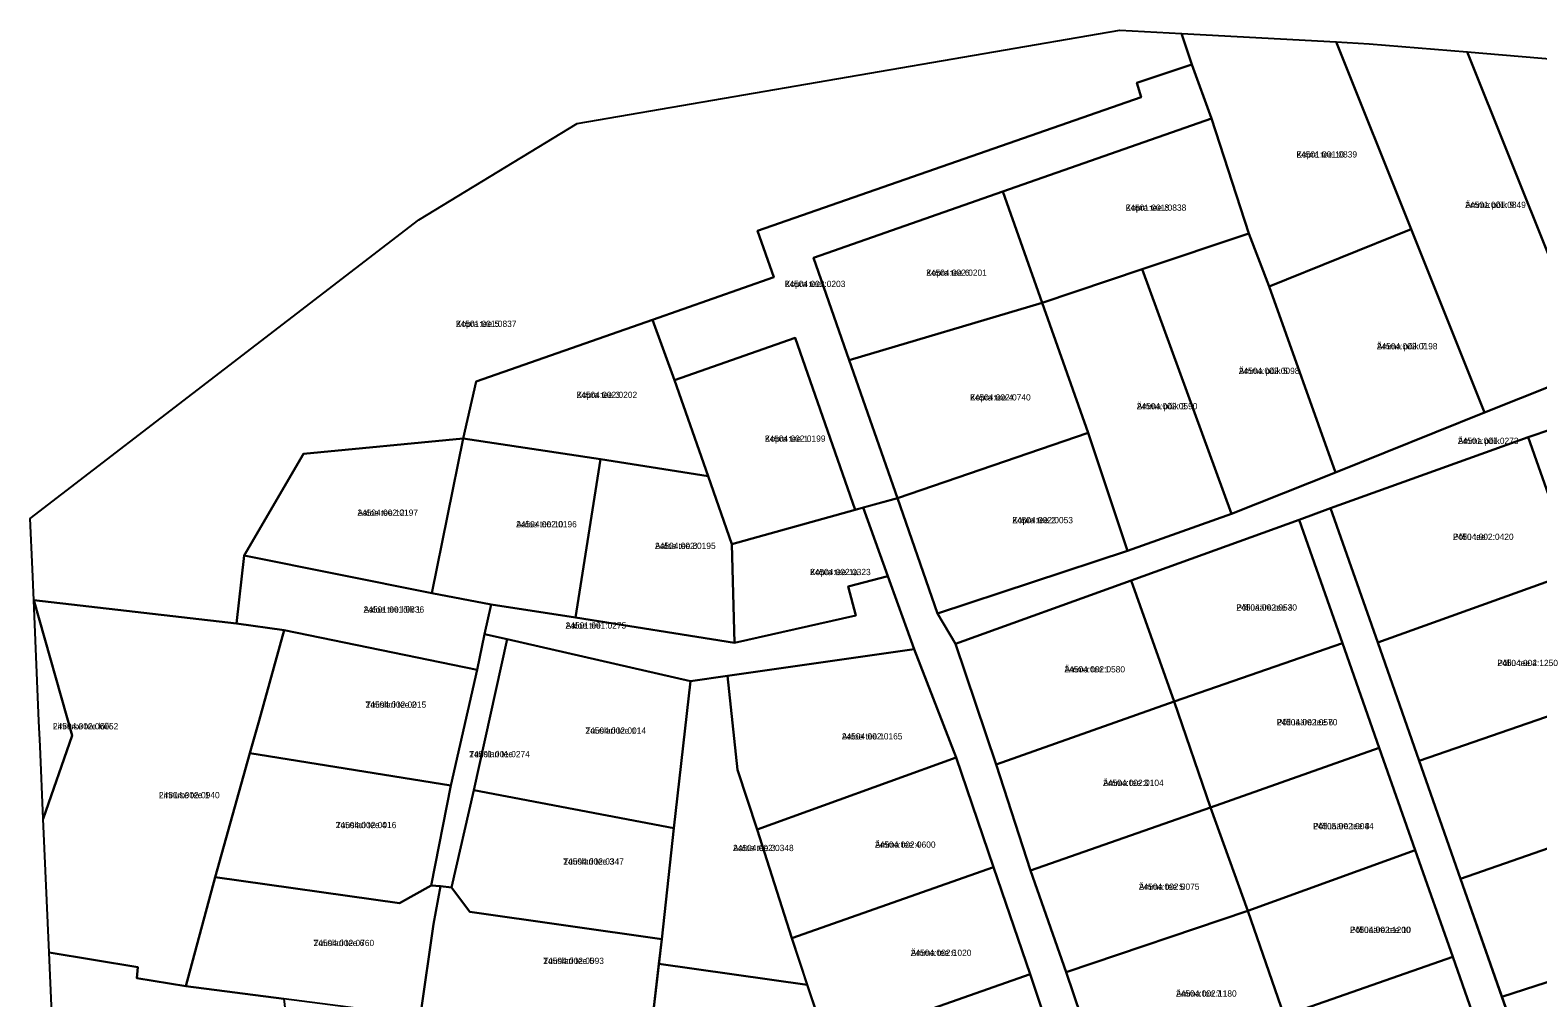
# Model space of a CAD drawing. Extents: x 551291 to 575799, y 6581704 to 6610137.
# Drawn here: x 551347 to 551707.6, y 6591626.4 to 6591857.9 of the extents above; entities that cross this region are included whole.
import ezdxf

# ---------------------------------------------------------------- set-up
doc = ezdxf.new("R2010")
doc.units = 0
for name, color, linetype in [('L_AADRESS', 7, 'Continuous'), ('PIIR', 7, 'Continuous'), ('TUNNUS', 7, 'Continuous')]:
    doc.layers.add(name, color=color, linetype=linetype)

msp = doc.modelspace()

# ---------------------------------------------------------------- linework, layer by layer
at = {"layer": 'PIIR'}
for points in [[(551347.57, 6591728.97), (551347.04, 6591741.05), (551440.02, 6591812.49), (551477.88, 6591835.59), (551607.64, 6591857.89), (551622.41, 6591857.07), (551624.87, 6591849.71), (551611.7, 6591845.29), (551612.75, 6591841.86), (551521.01, 6591809.87), (551524.9, 6591798.78), (551495.86, 6591788.6), (551453.68, 6591773.87), (551450.58, 6591760.19), (551412.45, 6591756.55), (551398.24, 6591732.22), (551396.38, 6591715.91), (551347.93, 6591721.53)], [(551624.87, 6591849.71), (551622.41, 6591857.07), (551659.41, 6591855.09), (551677.36, 6591810.31), (551643.33, 6591796.6), (551638.53, 6591809.22), (551629.57, 6591836.72)], [(551677.36, 6591810.31), (551659.41, 6591855.09), (551667.28, 6591854.6), (551690.73, 6591852.67), (551721.09, 6591776.85), (551694.89, 6591766.39)], [(551721.09, 6591776.85), (551690.73, 6591852.67), (551725.49, 6591849.79), (551749.98, 6591788.42)], [(551495.86, 6591788.6), (551524.9, 6591798.78), (551521.01, 6591809.87), (551612.75, 6591841.86), (551611.7, 6591845.29), (551624.87, 6591849.71), (551629.57, 6591836.72), (551579.7, 6591819.3), (551534.39, 6591803.43), (551542.95, 6591778.94), (551554.48, 6591745.97), (551544.35, 6591743.14), (551529.97, 6591784.26), (551501.14, 6591774.18)], [(551589.06, 6591792.64), (551579.7, 6591819.3), (551629.57, 6591836.72), (551638.53, 6591809.22), (551612.95, 6591800.71)], [(551534.39, 6591803.43), (551579.7, 6591819.3), (551589.06, 6591792.64), (551542.95, 6591778.94)], [(551643.33, 6591796.6), (551677.36, 6591810.31), (551694.89, 6591766.39), (551659.24, 6591752.11)], [(551610.34, 6591726.23), (551568.31, 6591711.06), (551564.06, 6591718.33), (551609.5, 6591733.31), (551634.34, 6591742.15), (551659.24, 6591752.11), (551694.89, 6591766.39), (551721.09, 6591776.85), (551789.53, 6591804.25), (551796.45, 6591806.72), (551800.78, 6591794.36), (551794.87, 6591792.4), (551753.43, 6591777.63), (551710.93, 6591762.47), (551705.31, 6591760.5), (551658.03, 6591743.51), (551650.5, 6591740.76)], [(551659.24, 6591752.11), (551634.34, 6591742.15), (551612.95, 6591800.71), (551638.53, 6591809.22), (551643.33, 6591796.6)], [(551609.5, 6591733.31), (551600.09, 6591761.53), (551589.06, 6591792.64), (551612.95, 6591800.71), (551634.34, 6591742.15)], [(551542.95, 6591778.94), (551589.06, 6591792.64), (551600.09, 6591761.53), (551554.48, 6591745.97)], [(551450.58, 6591760.19), (551453.68, 6591773.87), (551495.86, 6591788.6), (551501.14, 6591774.18), (551509.18, 6591751.19), (551483.45, 6591755.25)], [(551501.14, 6591774.18), (551529.97, 6591784.26), (551544.35, 6591743.14), (551514.87, 6591734.92), (551509.18, 6591751.19)], [(551398.24, 6591732.22), (551412.45, 6591756.55), (551450.58, 6591760.19), (551443.08, 6591723.22)], [(551443.08, 6591723.22), (551450.58, 6591760.19), (551483.45, 6591755.25), (551477.46, 6591717.37), (551457.3, 6591720.53)], [(551554.48, 6591745.97), (551600.09, 6591761.53), (551609.5, 6591733.31), (551564.06, 6591718.33)], [(551716.61, 6591728.42), (551669.32, 6591711.4), (551658.03, 6591743.51), (551705.31, 6591760.5)], [(551477.46, 6591717.37), (551483.45, 6591755.25), (551509.18, 6591751.19), (551514.87, 6591734.92), (551515.5, 6591711.36)], [(551546.24, 6591743.67), (551552.15, 6591727.27), (551542.69, 6591724.76), (551544.52, 6591717.87), (551515.5, 6591711.36), (551514.87, 6591734.92), (551544.35, 6591743.14)], [(551650.5, 6591740.76), (551660.88, 6591711.22), (551620.62, 6591697.32), (551610.34, 6591726.23)], [(551396.38, 6591715.91), (551398.24, 6591732.22), (551443.08, 6591723.22), (551457.3, 6591720.53), (551455.69, 6591713.43), (551453.96, 6591704.88), (551407.79, 6591714.39)], [(551716.61, 6591728.42), (551726.77, 6591699.51), (551679.21, 6591683.1), (551669.32, 6591711.4)], [(551554.64, 6591720.44), (551558.47, 6591709.79), (551513.8, 6591703.41), (551504.97, 6591702.18), (551461.13, 6591712.17), (551455.69, 6591713.43), (551457.3, 6591720.53), (551477.46, 6591717.37), (551515.5, 6591711.36), (551544.52, 6591717.87), (551542.69, 6591724.76), (551552.15, 6591727.27)], [(551568.31, 6591711.06), (551610.34, 6591726.23), (551620.62, 6591697.32), (551578.04, 6591682.25)], [(551372.53, 6591631.12), (551372.81, 6591633.7), (551351.57, 6591637.27), (551350.19, 6591669.23), (551357.06, 6591689.12), (551347.93, 6591721.53), (551396.38, 6591715.91), (551407.79, 6591714.39), (551401.79, 6591692.75), (551399.59, 6591684.89), (551391.3, 6591655.25), (551384.29, 6591629.18)], [(551347.93, 6591721.53), (551357.06, 6591689.12), (551350.19, 6591669.23), (551349.41, 6591686.57), (551349.15, 6591692.59)], [(551447.66, 6591677.18), (551399.59, 6591684.89), (551401.79, 6591692.75), (551407.79, 6591714.39), (551453.96, 6591704.88)], [(551455.69, 6591713.43), (551461.13, 6591712.17), (551453.12, 6591676.08), (551447.8, 6591652.81), (551445.21, 6591653.11), (551442.98, 6591653.31), (551447.66, 6591677.18), (551453.96, 6591704.88)], [(551504.97, 6591702.18), (551500.98, 6591666.99), (551453.12, 6591676.08), (551461.13, 6591712.17)], [(551520.89, 6591666.64), (551516.23, 6591680.97), (551513.8, 6591703.41), (551558.47, 6591709.79), (551568.54, 6591683.91)], [(551620.62, 6591697.32), (551660.88, 6591711.22), (551669.67, 6591686.22), (551629.31, 6591671.96)], [(551513.8, 6591703.41), (551516.23, 6591680.97), (551520.89, 6591666.64), (551529.2, 6591640.7), (551532.9, 6591629.5), (551497.39, 6591634.52), (551498.08, 6591640.47), (551500.98, 6591666.99), (551504.97, 6591702.18)], [(551679.21, 6591683.1), (551726.77, 6591699.51), (551736.71, 6591671.46), (551689.09, 6591654.87)], [(551620.62, 6591697.32), (551629.31, 6591671.96), (551586.29, 6591656.84), (551578.04, 6591682.25)], [(551399.59, 6591684.89), (551447.66, 6591677.18), (551442.98, 6591653.31), (551435.4, 6591649.08), (551391.3, 6591655.25)], [(551669.67, 6591686.22), (551678.29, 6591661.74), (551638.29, 6591647.25), (551629.31, 6591671.96)], [(551568.54, 6591683.91), (551577.47, 6591657.65), (551529.2, 6591640.7), (551520.89, 6591666.64)], [(551453.12, 6591676.08), (551500.98, 6591666.99), (551498.08, 6591640.47), (551452.19, 6591646.96), (551447.8, 6591652.81)], [(551629.31, 6591671.96), (551638.29, 6591647.25), (551594.85, 6591632.52), (551586.29, 6591656.84)], [(551736.71, 6591671.46), (551747.05, 6591642.15), (551699.01, 6591626.61), (551689.09, 6591654.87)], [(551687.28, 6591636.18), (551646.93, 6591622.13), (551638.29, 6591647.25), (551678.29, 6591661.74)], [(551384.29, 6591629.18), (551391.3, 6591655.25), (551435.4, 6591649.08), (551442.98, 6591653.31), (551445.21, 6591653.11), (551443.5, 6591644.04), (551440.39, 6591622.3), (551434.15, 6591622.77), (551407.68, 6591626.18)], [(551535.41, 6591621.9), (551529.2, 6591640.7), (551577.47, 6591657.65), (551586.18, 6591632.05), (551538.39, 6591615.24)], [(551447.8, 6591652.81), (551452.19, 6591646.96), (551498.08, 6591640.47), (551495.23, 6591615.91), (551467.98, 6591619.3), (551440.39, 6591622.3), (551443.5, 6591644.04), (551445.21, 6591653.11)], [(551594.85, 6591632.52), (551638.29, 6591647.25), (551646.93, 6591622.13), (551603.77, 6591606.12)], [(551747.05, 6591642.15), (551761.57, 6591600.94), (551713.82, 6591584.55), (551699.01, 6591626.61)], [(551351.57, 6591637.27), (551372.81, 6591633.7), (551372.53, 6591631.12), (551384.29, 6591629.18), (551407.68, 6591626.18), (551410.96, 6591598.44), (551352.92, 6591606.2)], [(551497.39, 6591634.52), (551532.9, 6591629.5), (551535.41, 6591621.9), (551521.44, 6591619.14), (551520.38, 6591607.66), (551508.5, 6591608.46), (551500.12, 6591615.64), (551495.23, 6591615.91)], [(551687.28, 6591636.18), (551696.01, 6591611.32), (551655.55, 6591597.25), (551646.93, 6591622.13)], [(551542.85, 6591600.08), (551538.39, 6591615.24), (551586.18, 6591632.05), (551598.27, 6591596.12), (551592.88, 6591594.66), (551573.73, 6591596.71), (551547.69, 6591599.39)]]:
    msp.add_lwpolyline(points, close=True, dxfattribs=at)
for points in [[(551716.61, 6591728.42), (551705.31, 6591760.5), (551710.93, 6591762.47)], [(551598.27, 6591596.12), (551586.18, 6591632.05), (551577.47, 6591657.65), (551568.54, 6591683.91), (551558.47, 6591709.79), (551552.15, 6591727.27), (551546.24, 6591743.67), (551554.48, 6591745.97), (551564.06, 6591718.33), (551568.31, 6591711.06), (551578.04, 6591682.25), (551586.29, 6591656.84), (551594.85, 6591632.52), (551603.77, 6591606.12)], [(551725.48, 6591441.18), (551668.18, 6591422.91), (551665.24, 6591433.64), (551713.14, 6591445.37), (551704.69, 6591470.03), (551696.54, 6591495.42), (551699.95, 6591525.82), (551707.01, 6591557.48), (551709.63, 6591572.58), (551704.82, 6591586.26), (551696.01, 6591611.32), (551687.28, 6591636.18), (551678.29, 6591661.74), (551669.67, 6591686.22), (551660.88, 6591711.22), (551650.5, 6591740.76), (551658.03, 6591743.51), (551669.32, 6591711.4), (551679.21, 6591683.1), (551689.09, 6591654.87), (551713.82, 6591584.55)]]:
    msp.add_lwpolyline(points, dxfattribs=at)

# ---------------------------------------------------------------- texts
at = {"layer": 'L_AADRESS'}
for s, p in [('Kopra tee 10', (551649.88, 6591827.42)), ('Kopra tee 8', (551609.04, 6591814.68)), ('Ämma põik 9', (551690.25, 6591815.36)), ('Kopra tee 6', (551561.34, 6591799.12)), ('Kopra tee', (551527.51, 6591796.43)), ('Kopra tee 5', (551448.85, 6591786.9)), ('Ämma põik 7', (551669.11, 6591781.52)), ('Ämma põik 5', (551636.1, 6591775.63)), ('Kopra tee 3', (551477.71, 6591769.9)), ('Kopra tee 4', (551571.83, 6591769.3)), ('Ämma põik 3', (551611.7, 6591767.19)), ('Kopra tee 1', (551522.75, 6591759.42)), ('Ämma põik', (551688.5, 6591758.89)), ('Aaloe tee 12', (551425.3, 6591741.71)), ('Aaloe tee 10', (551463.27, 6591738.94)), ('Kopra tee 2', (551581.93, 6591739.93)), ('Aaloe tee 8', (551496.48, 6591733.78)), ('Põllu tee 2', (551687.32, 6591735.95)), ('Kopra tee 1a', (551533.56, 6591727.52)), ('Põlluääre tee 4', (551635.51, 6591719.04)), ('Aaloe tee lõik 1', (551426.77, 6591718.55)), ('Aaloe tee', (551475.09, 6591714.73)), ('Ämma tee 1', (551594.39, 6591704.24)), ('Põllu tee 4', (551697.93, 6591705.76)), ('Tuuslari tee 2', (551427.26, 6591695.79)), ('Linnuse tee lõik 2', (551352.5, 6591690.61)), ('Põlluääre tee 6', (551645.18, 6591691.59)), ('Tuuslari tee 1', (551479.83, 6591689.58)), ('Aaloe tee 1', (551541.16, 6591688.21)), ('Tuuslari tee', (551452.05, 6591683.96)), ('Ämma tee 3', (551603.64, 6591677.08)), ('Linnuse tee 1', (551377.86, 6591674.15)), ('Tuuslari tee 4', (551420.12, 6591666.99)), ('Põlluääre tee 8', (551653.87, 6591666.74)), ('Aaloe tee 3', (551515.14, 6591661.5)), ('Ämma tee 4', (551549.08, 6591662.3)), ('Tuuslari tee 3', (551474.54, 6591658.27)), ('Ämma tee 5', (551612.19, 6591652.24)), ('Põlluääre tee 10', (551662.69, 6591641.93)), ('Tuuslari tee 6', (551414.81, 6591638.78)), ('Ämma tee 6', (551557.65, 6591636.44)), ('Tuuslari tee 5', (551469.76, 6591634.51)), ('Ämma tee 7', (551621.09, 6591626.69))]:
    msp.add_text(s, height=1.5, dxfattribs=at).set_placement(p)
at = {"layer": 'TUNNUS'}
for s, p in [('24501:001:0839', (551649.88, 6591827.42)), ('24501:001:0838', (551609.04, 6591814.68)), ('24501:001:0849', (551690.25, 6591815.36)), ('24504:002:0201', (551561.34, 6591799.12)), ('24504:002:0203', (551527.51, 6591796.43)), ('24501:001:0837', (551448.85, 6591786.9)), ('24504:002:0198', (551669.11, 6591781.52)), ('24504:002:0098', (551636.1, 6591775.63)), ('24504:002:0202', (551477.71, 6591769.9)), ('24504:002:0740', (551571.83, 6591769.3)), ('24504:002:0590', (551611.7, 6591767.19)), ('24504:002:0199', (551522.75, 6591759.42)), ('24501:001:0273', (551688.5, 6591758.89)), ('24504:002:0197', (551425.3, 6591741.71)), ('24504:002:0196', (551463.27, 6591738.94)), ('24504:002:0053', (551581.93, 6591739.93)), ('24504:002:0195', (551496.48, 6591733.78)), ('24504:002:0420', (551687.32, 6591735.95)), ('24504:002:0323', (551533.56, 6591727.52)), ('24504:002:0530', (551635.51, 6591719.04)), ('24501:001:0836', (551426.77, 6591718.55)), ('24501:001:0275', (551475.09, 6591714.73)), ('24504:002:0580', (551594.39, 6591704.24)), ('24504:002:1250', (551697.93, 6591705.76)), ('24504:002:0015', (551427.26, 6591695.79)), ('24504:002:0605', (551352.5, 6591690.61)), ('24504:002:0570', (551645.18, 6591691.59)), ('24504:002:0014', (551479.83, 6591689.58)), ('24504:002:0165', (551541.16, 6591688.21)), ('24501:001:0274', (551452.05, 6591683.96)), ('24504:002:0104', (551603.64, 6591677.08)), ('24504:002:0940', (551377.86, 6591674.15)), ('24504:002:0016', (551420.12, 6591666.99)), ('24505:002:0044', (551653.87, 6591666.74)), ('24504:002:0348', (551515.14, 6591661.5)), ('24504:002:0600', (551549.08, 6591662.3)), ('24504:002:0347', (551474.54, 6591658.27)), ('24504:002:0075', (551612.19, 6591652.24)), ('24504:002:1200', (551662.69, 6591641.93)), ('24504:002:0760', (551414.81, 6591638.78)), ('24504:002:1020', (551557.65, 6591636.44)), ('24504:002:0093', (551469.76, 6591634.51)), ('24504:002:1180', (551621.09, 6591626.69))]:
    msp.add_text(s, height=1.5, dxfattribs=at).set_placement(p)

doc.saveas('drawing.dxf')
